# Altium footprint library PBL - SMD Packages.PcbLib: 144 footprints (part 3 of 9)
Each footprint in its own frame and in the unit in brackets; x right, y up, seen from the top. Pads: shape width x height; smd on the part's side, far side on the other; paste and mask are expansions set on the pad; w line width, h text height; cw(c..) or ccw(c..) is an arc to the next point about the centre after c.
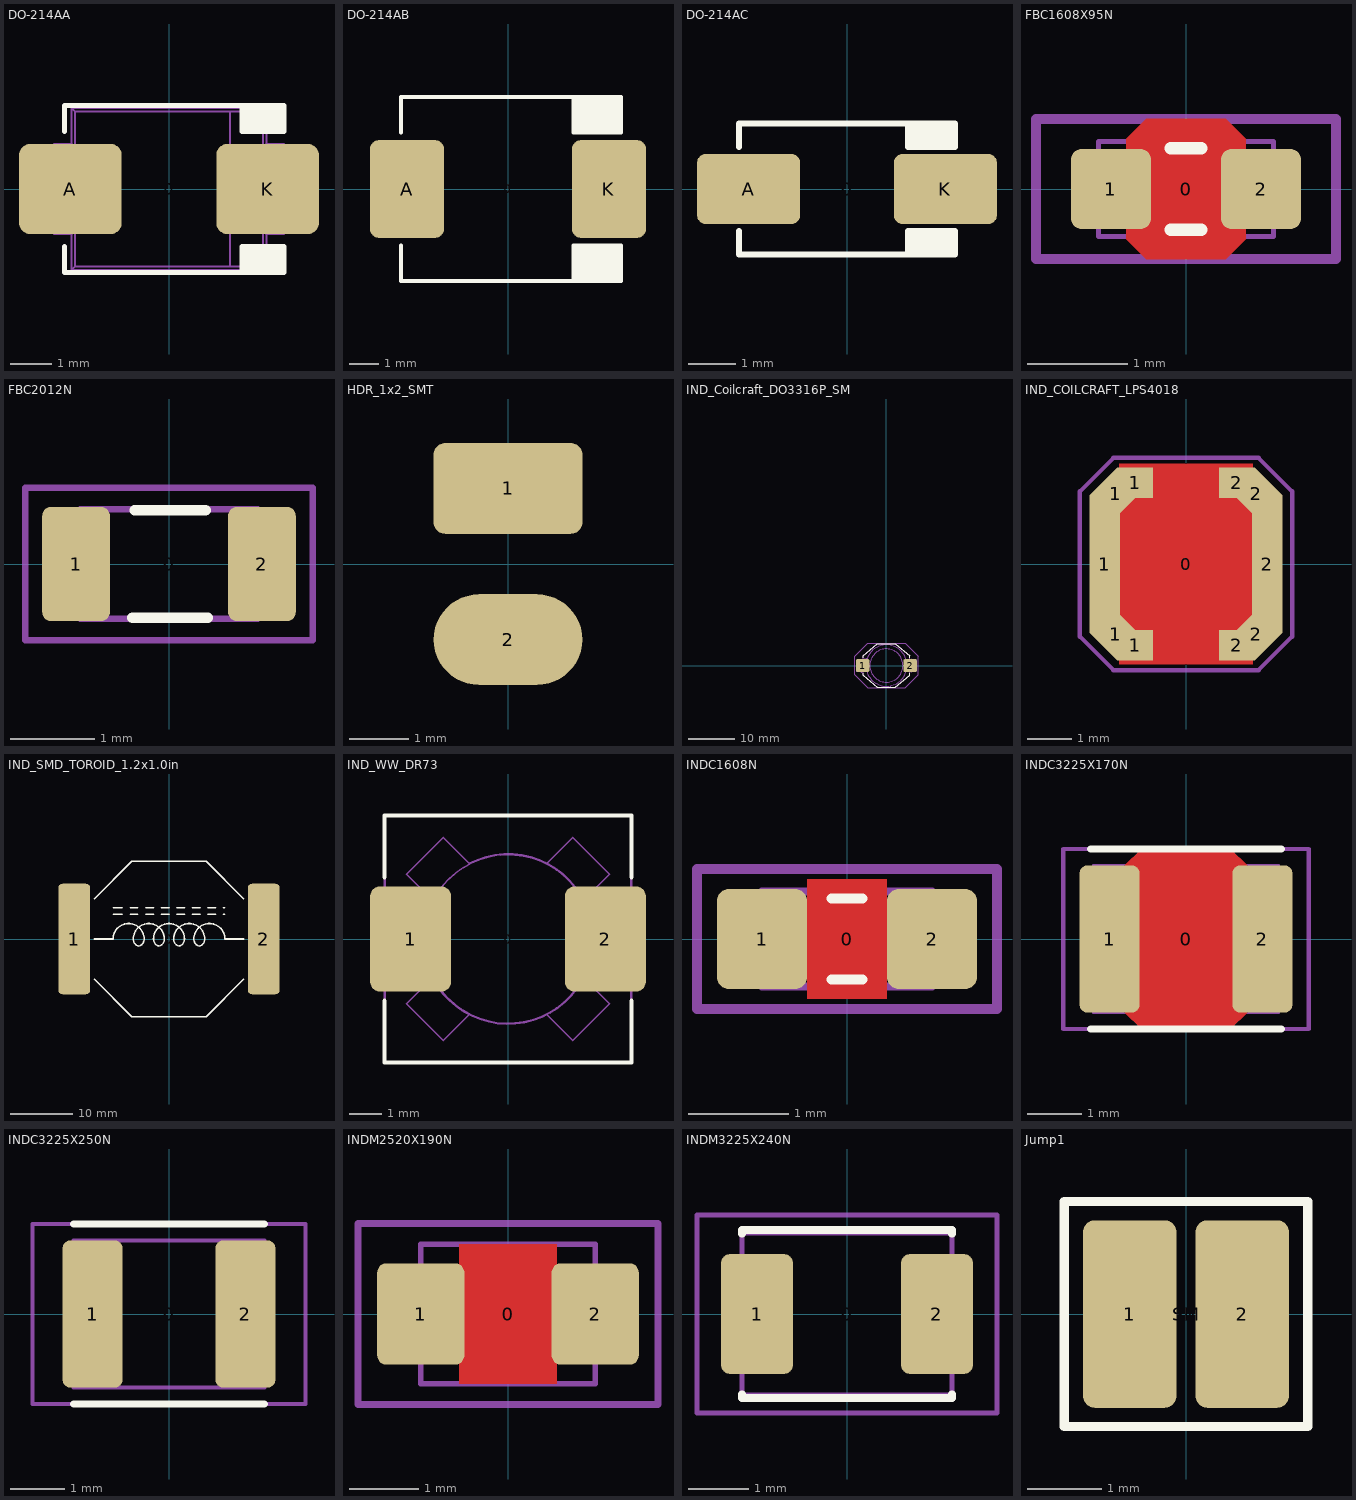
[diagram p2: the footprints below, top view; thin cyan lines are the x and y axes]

## DO-214AA [mm] "JEDEC DO214 variation AA. SMB"
height 2.65
pads (3):
  round 0.508 on Mech15: 0(0,0)
  rrect25% 2.5x2.2 smd: A(-2.4,0) K(2.4,0)
Top Overlay:
  region: 1.778,1.397 1.778,2.032 2.794,2.032 2.794,1.397
  region: 1.778,-1.397 1.778,-2.032 2.794,-2.032 2.794,-1.397
  lines w0.127: -2.54,-1.397 -2.54,-2.032 1.778,-2.032 ; -2.54,1.397 -2.54,2.032 1.778,2.032 ; 1.778,-2.032 1.778,-1.397 2.794,-1.397 2.794,-2.032 1.778,-2.032 ; 1.778,2.032 2.794,2.032 2.794,1.397 1.778,1.397 1.778,2.032
13 - 3D Top Side:
  lines w0.05: -2.375,-1.1 -2.375,-1.973 ; -2.375,1.1 -2.375,1.973 ; 2.375,-1.1 2.375,-1.973 ; 2.375,1.1 2.375,1.973 ; -2.375,-1.973 -2.373,-1.975 2.373,-1.975 2.375,-1.973 ; -2.375,-1.973 -2.285,-1.883 ; -2.375,1.973 -2.373,1.975 2.373,1.975 2.375,1.973 ; -2.375,1.973 -2.285,1.883 ; -2.285,-1.883 1.485,-1.884 ; -2.285,-1.883 -2.285,1.883 ; -2.285,1.883 1.485,1.884 ; 1.485,-1.884 2.285,-1.884 ; 1.485,-1.884 1.485,1.884 ; 1.485,1.884 2.285,1.884 ; 2.285,-1.884 2.285,1.884 ; 2.285,-1.884 2.375,-1.973 ; 2.285,1.884 2.375,1.973 ; -2.8,-1.1 -2.356,-1.1 -2.356,1.1 -2.8,1.1 -2.8,-1.1 ; 2.356,-1.1 2.8,-1.1 2.8,1.1 2.356,1.1 2.356,-1.1
3D body "DO-214AA.STEP": height 2.62, standoff 0, extent -2.8,-1.975 2.8,1.975

## DO-214AB [mm] "JEDEC DO214 variation AB. SMC"
height 2.5
pads (3):
  round 0.508 on Mech15: 0(0,0)
  rrect25% 2.5x3.3 smd: A(-3.4,0) K(3.4,0)
Top Overlay:
  rectangle: 2.2,1.9 3.8,3.1
  rectangle: 2.2,-3.1 3.8,-1.9
  lines w0.127: -3.6,-1.9 -3.6,-3.1 3.8,-3.1 3.8,-1.9 2.2,-1.9 2.2,-3.1 ; -3.6,1.9 -3.6,3.1 3.8,3.1 3.8,1.9 2.2,1.9 2.2,3.1
3D body: height 2.62, standoff 0.01, extent -3.975,-2.975 4.05,2.975

## DO-214AC [mm] "JEDEC DO214 variation AC. SMA"
height 2.5
pads (3):
  round 0.508 on Mech15: 0(0,0)
  rrect25% 2.2x1.5 smd: A(-2.1,0) K(2.1,0)
Top Overlay:
  rectangle: 1.3,-1.4 2.3,-0.9
  rectangle: 1.3,0.9 2.3,1.4
  lines w0.127: -2.3,-0.9 -2.3,-1.4 2.3,-1.4 2.3,-0.9 1.3,-0.9 1.3,-1.4 ; -2.3,0.9 -2.3,1.4 2.3,1.4 2.3,0.9 1.3,0.9 ; 1.3,0.911 1.3,1.4
3D body "SW3dPS-DO-214AC SMA.STEP": height 2.42, standoff 0.02, extent -2.6,-1.3 2.6,1.3

## FBC1608X95N [mm] "Chip Ferrite, Body 1.6x0.8mm, 0603, IPC Medium Density"
height 0.95
pads (3):
  round 0.254 on Mech15: 0(0,0)
  rrect25% 0.8x0.8 smd: 1(-0.75,0) 2(0.75,0)
Top Layer:
  pour cut-out: -0.6,0.5 -0.4,0.7 0.4,0.7 0.6,0.5 0.6,-0.5 0.4,-0.7 -0.4,-0.7 -0.6,-0.5
Top Overlay:
  lines w0.127: -0.152,-0.406 0.152,-0.406 ; -0.152,0.406 0.152,0.406
13 - 3D Top Side:
  lines w0.05: -0.475,-0.475 -0.475,0.475 ; 0.475,-0.475 0.475,0.475 ; -0.875,-0.475 0.875,-0.475 0.875,0.475 -0.875,0.475 -0.875,-0.475
15 - Top Courtyards:
  lines w0.1: -1.5,-0.7 -1.5,0.7 1.5,0.7 1.5,-0.7 -1.5,-0.7
3D body "FBC1608X95N.STEP": height 0.95, standoff 0, extent -0.875,-0.475 0.875,0.475

## FBC2012N [mm] "Ferrite Bead Chip, Body 2.0x1.2mm, 0805, IPC Medium Density"
height 0.9
pads (3):
  round 0.508 on Mech15: 0(0,0)
  rrect25% 0.8x1.35 smd: 1(-1.1,0) 2(1.1,0)
Top Overlay:
  lines w0.127: -0.432,-0.635 0.457,-0.635 ; -0.406,0.635 0.432,0.635
13 - 3D Top Side:
  lines w0.076: -1.05,-0.65 -1.05,0.65 1.05,0.65 1.05,-0.65 -1.05,-0.65
15 - Top Courtyards:
  lines w0.076: -1.7,-0.9 -1.7,0.9 1.7,0.9 1.7,-0.9 -1.7,-0.9
3D body "FBC_0805.stp": height 0.9, standoff 0, extent -1,-0.625 1,0.625

## HDR_1x2_SMT [mm]
pads (2):
  rrect25% 2.5x1.524 smd: 1(0,1.27)
  oval 2.5x1.524 smd: 2(0,-1.27)

## IND_Coilcraft_DO3316P_SM [mil] "Wire-wound Power Inductor, 2-Leads, Body 12.95x9.4mm"
height 205
pads (3):
  round 20 on Mech15: 0(0,0)
  rrect25% 115x110 smd: 1(-202.5,0) 2(202.5,0)
Top Overlay:
  lines w6: -200,-65 -200,-82.84 -76.63,-185 76.63,-185 200,-82.84 200,-65 ; -200,65 -200,82.84 -76.63,185 76.63,185 200,82.84 200,65
13 - 3D Top Side:
  drawing of 272 lines, arcs and shapes, not listed
15 - Top Courtyards:
  lines w3: -270,-80 -160,-190 160,-190 270,-80 270,80 160,190 -160,190 -270,80 -270,-80
3D body "Pulse Inductor RR.STEP": height 172.5, standoff 0, extent -255.38,-185 255.2,185

## IND_COILCRAFT_LPS4018 [mm] "Shielded Power Inductor, Body 4.0x4.0x1.8mm"
height 1.8
pads (11):
  round 0.5 on Mech15: 0(0,0)
  rrect1% 0.7x3.124 smd: 1(-1.85,0) 2(1.85,0)
  rrect1% 0.786x0.902 smd rot 45: 1(-1.603,-1.603) 2(1.603,1.603)
  rrect1% 0.786x0.902 smd rot 135: 1(-1.603,1.603) 2(1.603,-1.603)
  rrect1% 0.812x0.7 smd: 1(-1.156,-1.85) 1(-1.156,1.85) 2(1.156,-1.85) 2(1.156,1.85)
Top Layer:
  pour cut-out: -1.524,2.286 1.524,2.286 1.524,-2.286 -1.524,-2.286
13 - 3D Top Side:
  lines w0.076: -2,-1.275 -1.275,-2 1.275,-2 2,-1.275 2,1.325 1.325,2 -1.325,2 -2,1.325 -2,-1.275
15 - Top Courtyards:
  lines w0.1: -2.413,-1.651 -2.413,1.651 -1.651,2.413 1.651,2.413 2.413,1.651 2.413,-1.651 1.651,-2.413 -1.651,-2.413 -2.413,-1.651
3D body "Inductor Coilcraft LPS4018.STEP": height 1.79, standoff -0.01, extent -2,-2 2,2

## IND_SMD_TOROID_1.2x1.0in [mm] "Inductor, Toroid, 30.5mm L x 25.4mm W x 13.5mm T"
height 13.5
pads (3):
  round 2.54 on Mech15: 0(0,0)
  rrect25% 5.1x17.8 smd: 1(-15.25,0) 2(15.25,0)
Top Overlay:
  lines w0.254: -12,-6.5 -6,-12.5 6,-12.5 12,-6.5 ; -12,0 -9,0 cw(c-6.5,0) -4,0 cw(c-5.25,0) -4.691,-1.118 cw(c-4.875,0) -5.059,-1.118 cw(c-4.5,0) -5.75,0 cw(c-3.25,0) -0.75,0 cw(c-2,0) -1.441,-1.118 cw(c-1.625,0) -1.809,-1.118 cw(c-1.25,0) -2.5,0 cw(c0,0) 2.5,0 cw(c1.25,0) 1.809,-1.118 cw(c1.625,0) 1.441,-1.118 cw(c2,0) 0.75,0 cw(c3.25,0) 5.75,0 cw(c4.5,0) 5.059,-1.118 cw(c4.875,0) 4.691,-1.118 cw(c5.25,0) 4,0 cw(c6.5,0) 9,0 12,0 ; -12,6.5 -6,12.5 6,12.5 12,6.5 ; -9,4 -7.5,4 ; -9,5 -7.5,5 ; -6.25,4 -5,4 ; -6.25,5 -5,5 ; -3.75,4 -2.5,4 ; -3.75,5 -2.5,5 ; -1.25,4 0,4 ; -1.25,5 0,5 ; 1.25,4 2.5,4 ; 1.25,5 2.5,5 ; 3.75,4 5,4 ; 3.75,5 5,5 ; 6.25,4 7.5,4 ; 6.25,5 7.5,5 ; 8.75,4 9,4 ; 8.75,5 9,5
3D body: height 12, standoff 5, extent -10,-10 10,10
3D body: height 3.5, standoff 1.5, extent -17,-12.5 17,12.5

## IND_WW_DR73 [mm] "Wire-wound power inductor, Cooper Bussmann DR73 series, IPC Medium Density"
height 3.55
pads (3):
  round 0.5 on Mech15: 0(0,0)
  rrect25% 2.5x3.25 smd: 1(-3,0) 2(3,0)
Top Overlay:
  lines w0.127: -3.81,-1.905 -3.81,-3.81 3.81,-3.81 3.81,-1.905 ; -3.81,1.905 -3.81,3.81 3.81,3.81 3.81,1.905
13 - 3D Top Side:
  circle w0.05: c0,0 r2.6
  lines w0.05: -2.574,-0.515 -2.574,-0.367 ; -2.574,0.367 -2.574,0.515 ; -2.346,-1.178 -2.346,-1.121 ; -2.346,1.121 -2.346,1.178 ; -2.273,-1.263 -2.334,-1.202 -3.129,-1.998 -1.998,-3.129 -1.202,-2.334 ; -2.273,1.263 -2.334,1.202 ; -2.202,-1.429 -2.184,-1.411 ; -2.202,1.429 -2.184,1.411 ; -1.429,-2.202 -1.411,-2.184 ; -1.263,-2.273 -1.202,-2.334 ; -1.197,-2.308 -1.202,-2.334 ; -0.237,2.589 -0.232,2.615 ; 0.232,-2.615 0.237,-2.589 ; 1.197,2.308 1.202,2.334 ; 1.202,-2.334 1.998,-3.129 3.129,-1.998 2.334,-1.202 2.273,-1.263 ; 1.263,2.273 1.202,2.334 ; 1.411,2.184 1.429,2.202 ; 2.184,-1.411 2.202,-1.429 ; 2.184,1.411 2.202,1.429 ; 2.273,1.263 2.334,1.202 3.129,1.998 1.998,3.129 1.202,2.334 ; 2.574,-0.515 2.574,-0.367 ; 2.574,0.367 2.574,0.515 ; -2.334,1.202 ccw(c0,0) -1.202,2.334 -1.998,3.129 -3.129,1.998 -2.334,1.202 ; -3.8,-3.8 -3.8,3.8 3.8,3.8 3.8,-3.8 -3.8,-3.8
15 - Top Courtyards:
  lines w0.076: -3.8,-3.8 3.8,-3.8 3.8,3.8 -3.8,3.8 -3.8,-3.8
3D body "Cooper Bussman DR73 Series Inductor.STEP": height 3.55, standoff 0, extent -3.8,-3.8 3.8,3.8

## INDC1608N [mm] "Chip bead, Body 1.6x0.8mm, 0603, IPC Medium Density"
height 0.8
pads (3):
  round 0.254 on Mech15: 0(0,0)
  rrect25% 0.9x1 smd: 1(-0.85,0) 2(0.85,0)
Top Layer:
  pour cut-out: -0.4,0.6 0.4,0.6 0.4,-0.6 -0.4,-0.6
Top Overlay:
  lines w0.102: -0.152,-0.406 0.152,-0.406 ; -0.152,0.406 0.152,0.406
13 - 3D Top Side:
  lines w0.076: -0.85,-0.475 -0.85,0.475 0.85,0.475 0.85,-0.475 -0.85,-0.475
15 - Top Courtyards:
  lines w0.1: -1.5,-0.7 -1.5,0.7 1.5,0.7 1.5,-0.7 -1.5,-0.7
3D body "INDC1608X80N.step": height 0.79, standoff -0.01, extent -0.8,-0.4 0.8,0.4

## INDC3225X170N [mm] "Chip Inductor, 2-Leads, Body 3.2x2.5mm, IPC Medium Density"
height 1.7
pads (3):
  round 0.508 on Mech15: 0(0,0)
  rrect25% 1.1x2.7 smd: 1(-1.4,0) 2(1.4,0)
Top Layer:
  pour cut-out: -1.125,1.35 -0.825,1.65 0.825,1.65 1.125,1.35 1.125,-1.35 0.825,-1.65 -0.825,-1.65 -1.125,-1.35
Top Overlay:
  lines w0.127: -1.75,-1.651 1.75,-1.651 ; -1.75,1.651 1.75,1.651
13 - 3D Top Side:
  lines w0.05: -1.7,-1.35 -1.7,1.35 1.7,1.35 1.7,-1.35 -1.7,-1.35
15 - Top Courtyards:
  lines w0.076: -2.25,-1.65 2.25,-1.65 2.25,1.65 -2.25,1.65 -2.25,-1.65
3D body "INDC3225X170N.STEP": height 1.7, standoff 0, extent -1.71,-1.36 1.71,1.36

## INDC3225X250N [mm] "Chip Inductor, 2-Leads, Body 3.2x2.5mm, IPC Medium Density"
height 2.7
pads (3):
  round 0.508 on Mech15: 0(0,0)
  rrect25% 1.1x2.7 smd: 1(-1.4,0) 2(1.4,0)
Top Overlay:
  lines w0.127: -1.75,-1.651 1.75,-1.651 ; -1.75,1.651 1.75,1.651
13 - 3D Top Side:
  lines w0.076: -1.75,-1.35 1.75,-1.35 1.75,1.35 -1.75,1.35 -1.75,-1.35
15 - Top Courtyards:
  lines w0.076: -2.5,-1.65 2.5,-1.65 2.5,1.65 -2.5,1.65 -2.5,-1.65
3D body "INDC3225X250N.STEP": height 2.7, standoff 0, extent -1.7,-1.35 1.7,1.35

## INDM2520X190N [mm] "Inductor, molded body 2.5x2.0mm"
height 1.9
pads (3):
  round 0.508 on Mech15: 0(0,0)
  rrect20% 1.25x1.45 smd: 1(-1.25,0) 2(1.25,0)
Top Layer:
  pour cut-out: -0.7,1 0.7,1 0.7,-1 -0.7,-1
13 - 3D Top Side:
  lines w0.076: -1.25,-1 1.25,-1 1.25,1 -1.25,1 -1.25,-1
15 - Top Courtyards:
  lines w0.1: -2.15,-1.3 2.15,-1.3 2.15,1.3 -2.15,1.3 -2.15,-1.3
3D body "INDM2520X190N.STEP": height 1.79, standoff -0.01, extent -1.25,-1 1.25,1

## INDM3225X240N [mm] "Molded Inductor, 2-Leads, Body 3.2x2.5mm, IPC Medium Density"
height 2.4
pads (3):
  round 0.508 on Mech15: 0(0,0)
  rrect25% 1.2x2 smd: 1(-1.5,0) 2(1.5,0)
Top Overlay:
  lines w0.127: -1.75,-1.338 -1.75,-1.4 1.75,-1.4 1.75,-1.338 ; -1.75,1.338 -1.75,1.4 1.75,1.4 1.75,1.338
13 - 3D Top Side:
  lines w0.076: -1.75,-1.35 1.75,-1.35 1.75,1.35 -1.75,1.35 -1.75,-1.35
15 - Top Courtyards:
  lines w0.076: -2.5,-1.65 2.5,-1.65 2.5,1.65 -2.5,1.65 -2.5,-1.65
3D body "INDM3225X240N.STEP": height 2.4, standoff 0, extent -1.79,-1.35 1.79,1.35

## Jump1 [mil] "SMT Battery jumper pads"
pads (3):
  rrect25% 50x100 smd: 1(-30,0) 2(30,0)
  rrect25% 118x108 on Top Solder: SM(0,0)
Top Overlay:
  lines w5: -65,-60 65,-60 65,60 -65,60 -65,-60
13 - 3D Top Side:
  lines w3: -65,-60 65,-60 65,60 -65,60 -65,-60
